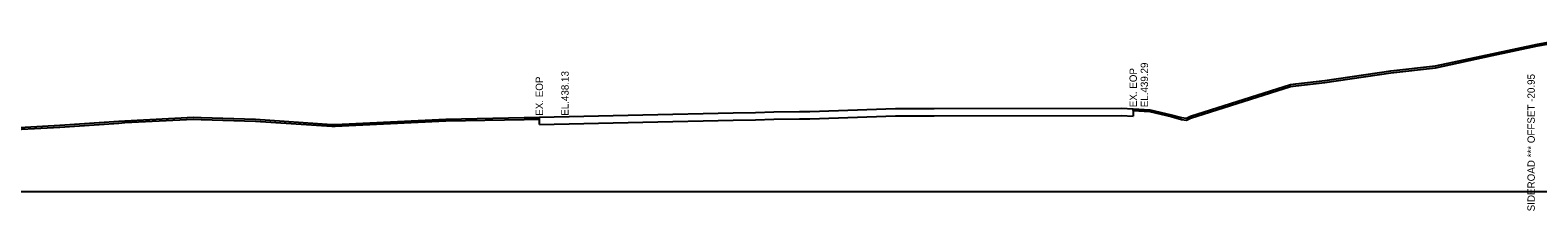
# Model space of a CAD drawing. Extents: x -26 to 803, y -27 to 3586.
# Drawn here: x 173.7 to 379, y 497.4 to 522 of the extents above; entities that cross this region are included whole.
import ezdxf

# ---------------------------------------------------------------- set-up
doc = ezdxf.new("R2010")
doc.units = 0
for name, color, linetype in [('DESIGN - SHEET - Light Grid', 7, 'Continuous'), ('DESIGN - TYPICAL - Text', 7, 'Continuous'), ('SURVEY - GROUND - Bottom of Topsoil Layer', 7, 'Continuous'), ('SURVEY - GROUND - Existing Pavement Layer', 7, 'Continuous'), ('SURVEY - GROUND - Existing Pavement Text', 7, 'Continuous'), ('SURVEY - GROUND - Top of Ground', 7, 'Continuous')]:
    doc.layers.add(name, color=color, linetype=linetype)

msp = doc.modelspace()

# ---------------------------------------------------------------- linework, layer by layer
at = {"layer": 'DESIGN - SHEET - Light Grid'}
msp.add_line((0, 500), (400, 500), dxfattribs=at)
at = {"layer": 'SURVEY - GROUND - Bottom of Topsoil Layer'}
for p, q in [((379, 519.85), (389.55, 521.76)), ((372.82, 518.55), (379, 519.85)), ((365.07, 516.87), (372.82, 518.55)), ((350.01, 514.88), (359.03, 516.2)), ((359.03, 516.2), (365.07, 516.87)), ((331.74, 510.01), (345.35, 514.33)), ((345.35, 514.33), (346.06, 514.43)), ((346.06, 514.43), (350.01, 514.88)), ((323.93, 511.04), (323.93, 511.29)), ((177.79, 508.8), (185.83, 509.34)), ((185.83, 509.34), (186.61, 509.4)), ((186.61, 509.4), (195.99, 509.88)), ((195.99, 509.88), (197.01, 509.83)), ((197.01, 509.83), (204.43, 509.61)), ((204.43, 509.61), (214.82, 508.9)), ((215.28, 508.9), (230.36, 509.63)), ((230.36, 509.63), (241, 509.84)), ((241, 509.84), (242.08, 509.85)), ((242.08, 509.85), (243.07, 509.88)), ((243.07, 509.88), (243.07, 510.13)), ((323.93, 511.04), (326.18, 510.91)), ((326.18, 510.91), (329.08, 510.22)), ((329.08, 510.22), (330.51, 509.84)), ((330.51, 509.84), (331.19, 509.75)), ((331.19, 509.75), (331.74, 510.01)), ((168.28, 508.27), (177.79, 508.8)), ((214.82, 508.9), (215.28, 508.9))]:
    msp.add_line(p, q, dxfattribs=at)
at = {"layer": 'SURVEY - GROUND - Existing Pavement Layer'}
for p, q in [((323.93, 511.29), (323.93, 510.29)), ((243.07, 509.13), (243.07, 510.13)), ((243.07, 509.13), (257.15, 509.47)), ((257.15, 509.47), (269.47, 509.73)), ((269.47, 509.73), (272.5, 509.8)), ((272.5, 509.8), (275.01, 509.85)), ((275.01, 509.85), (278.51, 509.9)), ((278.51, 509.9), (279.89, 509.91)), ((279.89, 509.91), (291.56, 510.32)), ((291.56, 510.32), (292.13, 510.33)), ((292.13, 510.33), (296.82, 510.33)), ((296.82, 510.33), (322.32, 510.37)), ((322.32, 510.37), (323.93, 510.29))]:
    msp.add_line(p, q, dxfattribs=at)
at = {"layer": 'SURVEY - GROUND - Top of Ground'}
msp.add_lwpolyline([(168.28, 508.52), (177.79, 509.05), (185.83, 509.59), (186.61, 509.65), (195.99, 510.13), (197.01, 510.08), (204.43, 509.86), (214.82, 509.15), (215.28, 509.15), (230.36, 509.88), (241, 510.09), (242.08, 510.1), (243.07, 510.13), (257.15, 510.47), (269.47, 510.73), (272.5, 510.8), (275.01, 510.85), (278.51, 510.9), (279.89, 510.91), (291.56, 511.32), (292.13, 511.33), (296.82, 511.33), (322.32, 511.37), (323.93, 511.29), (326.18, 511.16), (329.08, 510.47), (330.51, 510.09), (331.19, 510), (331.74, 510.26), (345.35, 514.58), (346.06, 514.68), (350.01, 515.13), (359.03, 516.45), (365.07, 517.12), (372.82, 518.8), (379, 520.1), (389.55, 522.01)], dxfattribs=at)

# ---------------------------------------------------------------- texts
at = {"layer": 'DESIGN - TYPICAL - Text'}
msp.add_text('SIDEROAD *** OFFSET -20.95', height=1, rotation=90, dxfattribs=at).set_placement((378.61, 497.3))
at = {"layer": 'SURVEY - GROUND - Existing Pavement Text'}
for s, p in [('EL.439.29', (325.95, 511.49)), ('EX. EOP', (243.57, 510.33)), ('EL.438.13', (247.06, 510.33)), ('EX. EOP', (324.43, 511.49))]:
    msp.add_text(s, height=1, rotation=90, dxfattribs=at).set_placement(p)

doc.saveas('drawing.dxf')
